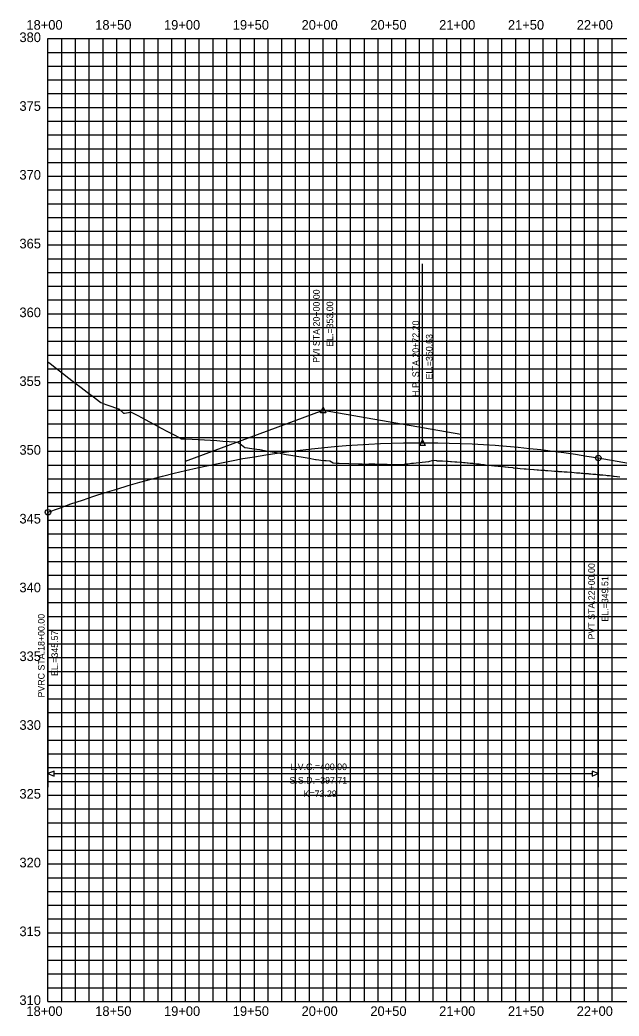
# Model space of a CAD drawing. Extents: x -797 to 1040, y -6256 to -5532.
# Drawn here: x 202 to 637, y -6256 to -5532 of the extents above; entities that cross this region are included whole.
import ezdxf

# ---------------------------------------------------------------- set-up
doc = ezdxf.new("R2010")
doc.units = 0
for name, color, linetype in [('CT_Pro_Grid_Frame', 7, 'Continuous'), ('CT_Pro_screen_Major', 7, 'Continuous'), ('CT_Pro_screen_Minor', 7, 'Continuous'), ('HM-SMOD-USR DEF1', 7, 'Continuous'), ('HR-GMSC-HOR_VER ALN', 7, 'Continuous'), ('HR-GMSC-PVCPVT SYMB', 7, 'Continuous'), ('HR-GPRO-PVCPVIPVT LDR', 7, 'Continuous'), ('HR-GPRO-PVCPVT TXT', 7, 'Continuous'), ('HR-GPRO-PVI SYMB', 7, 'Continuous'), ('HR-GPRO-PVI TXT', 7, 'Continuous'), ('HR-GPRO-STA_ELEV GRID TXT', 7, 'Continuous')]:
    doc.layers.add(name, color=color, linetype=linetype)

msp = doc.modelspace()

# ---------------------------------------------------------------- linework, layer by layer
at = {"layer": 'CT_Pro_Grid_Frame'}
for p, q in [((222.2, -5545.62), (1022.2, -5545.62)), ((222.2, -6245.62), (222.2, -5545.62)), ((222.2, -6245.62), (1022.2, -6245.62))]:
    msp.add_line(p, q, dxfattribs=at)
at = {"layer": 'CT_Pro_screen_Major'}
for p, q in [((272.2, -6245.62), (272.2, -5545.62)), ((322.2, -6245.62), (322.2, -5545.62)), ((372.2, -6245.62), (372.2, -5545.62)), ((422.2, -6245.62), (422.2, -5545.62)), ((472.2, -6245.62), (472.2, -5545.62)), ((522.2, -6245.62), (522.2, -5545.62)), ((572.2, -6245.62), (572.2, -5545.62)), ((622.2, -6245.62), (622.2, -5545.62)), ((222.2, -5595.62), (1022.2, -5595.62)), ((222.2, -5645.62), (1022.2, -5645.62)), ((222.2, -5695.62), (1022.2, -5695.62)), ((222.2, -5745.62), (1022.2, -5745.62)), ((222.2, -5795.62), (1022.2, -5795.62)), ((222.2, -5845.62), (1022.2, -5845.62)), ((222.2, -5895.62), (1022.2, -5895.62)), ((222.2, -5945.62), (1022.2, -5945.62)), ((222.2, -5995.62), (1022.2, -5995.62)), ((222.2, -6045.62), (1022.2, -6045.62)), ((222.2, -6095.62), (1022.2, -6095.62)), ((222.2, -6145.62), (1022.2, -6145.62)), ((222.2, -6195.62), (1022.2, -6195.62))]:
    msp.add_line(p, q, dxfattribs=at)
at = {"layer": 'CT_Pro_screen_Minor'}
for p, q in [((232.2, -6245.62), (232.2, -5545.62)), ((242.2, -6245.62), (242.2, -5545.62)), ((252.2, -6245.62), (252.2, -5545.62)), ((262.2, -6245.62), (262.2, -5545.62)), ((282.2, -6245.62), (282.2, -5545.62)), ((292.2, -6245.62), (292.2, -5545.62)), ((302.2, -6245.62), (302.2, -5545.62)), ((312.2, -6245.62), (312.2, -5545.62)), ((332.2, -6245.62), (332.2, -5545.62)), ((342.2, -6245.62), (342.2, -5545.62)), ((352.2, -6245.62), (352.2, -5545.62)), ((362.2, -6245.62), (362.2, -5545.62)), ((382.2, -6245.62), (382.2, -5545.62)), ((392.2, -6245.62), (392.2, -5545.62)), ((402.2, -6245.62), (402.2, -5545.62)), ((412.2, -6245.62), (412.2, -5545.62)), ((432.2, -6245.62), (432.2, -5545.62)), ((442.2, -6245.62), (442.2, -5545.62)), ((452.2, -6245.62), (452.2, -5545.62)), ((462.2, -6245.62), (462.2, -5545.62)), ((482.2, -6245.62), (482.2, -5545.62)), ((492.2, -6245.62), (492.2, -5545.62)), ((502.2, -6245.62), (502.2, -5545.62)), ((512.2, -6245.62), (512.2, -5545.62)), ((532.2, -6245.62), (532.2, -5545.62)), ((542.2, -6245.62), (542.2, -5545.62)), ((552.2, -6245.62), (552.2, -5545.62)), ((562.2, -6245.62), (562.2, -5545.62)), ((582.2, -6245.62), (582.2, -5545.62)), ((592.2, -6245.62), (592.2, -5545.62)), ((602.2, -6245.62), (602.2, -5545.62)), ((612.2, -6245.62), (612.2, -5545.62)), ((632.2, -6245.62), (632.2, -5545.62)), ((222.2, -5555.62), (1022.2, -5555.62)), ((222.2, -5565.62), (1022.2, -5565.62)), ((222.2, -5575.62), (1022.2, -5575.62)), ((222.2, -5585.62), (1022.2, -5585.62)), ((222.2, -5605.62), (1022.2, -5605.62)), ((222.2, -5615.62), (1022.2, -5615.62)), ((222.2, -5625.62), (1022.2, -5625.62)), ((222.2, -5635.62), (1022.2, -5635.62)), ((222.2, -5655.62), (1022.2, -5655.62)), ((222.2, -5665.62), (1022.2, -5665.62)), ((222.2, -5675.62), (1022.2, -5675.62)), ((222.2, -5685.62), (1022.2, -5685.62)), ((222.2, -5705.62), (1022.2, -5705.62)), ((222.2, -5715.62), (1022.2, -5715.62)), ((222.2, -5725.62), (1022.2, -5725.62)), ((222.2, -5735.62), (1022.2, -5735.62)), ((222.2, -5755.62), (1022.2, -5755.62)), ((222.2, -5765.62), (1022.2, -5765.62)), ((222.2, -5775.62), (1022.2, -5775.62)), ((222.2, -5785.62), (1022.2, -5785.62)), ((222.2, -5805.62), (1022.2, -5805.62)), ((222.2, -5815.62), (1022.2, -5815.62)), ((222.2, -5825.62), (1022.2, -5825.62)), ((222.2, -5835.62), (1022.2, -5835.62)), ((222.2, -5855.62), (1022.2, -5855.62)), ((222.2, -5865.62), (1022.2, -5865.62)), ((222.2, -5875.62), (1022.2, -5875.62)), ((222.2, -5885.62), (1022.2, -5885.62)), ((222.2, -5905.62), (1022.2, -5905.62)), ((222.2, -5915.62), (1022.2, -5915.62)), ((222.2, -5925.62), (1022.2, -5925.62)), ((222.2, -5935.62), (1022.2, -5935.62)), ((222.2, -5955.62), (1022.2, -5955.62)), ((222.2, -5965.62), (1022.2, -5965.62)), ((222.2, -5975.62), (1022.2, -5975.62)), ((222.2, -5985.62), (1022.2, -5985.62)), ((222.2, -6005.62), (1022.2, -6005.62)), ((222.2, -6015.62), (1022.2, -6015.62)), ((222.2, -6025.62), (1022.2, -6025.62)), ((222.2, -6035.62), (1022.2, -6035.62)), ((222.2, -6055.62), (1022.2, -6055.62)), ((222.2, -6065.62), (1022.2, -6065.62)), ((222.2, -6075.62), (1022.2, -6075.62)), ((222.2, -6085.62), (1022.2, -6085.62)), ((222.2, -6105.62), (1022.2, -6105.62)), ((222.2, -6115.62), (1022.2, -6115.62)), ((222.2, -6125.62), (1022.2, -6125.62)), ((222.2, -6135.62), (1022.2, -6135.62)), ((222.2, -6155.62), (1022.2, -6155.62)), ((222.2, -6165.62), (1022.2, -6165.62)), ((222.2, -6175.62), (1022.2, -6175.62)), ((222.2, -6185.62), (1022.2, -6185.62)), ((222.2, -6205.62), (1022.2, -6205.62)), ((222.2, -6215.62), (1022.2, -6215.62)), ((222.2, -6225.62), (1022.2, -6225.62)), ((222.2, -6235.62), (1022.2, -6235.62))]:
    msp.add_line(p, q, dxfattribs=at)
at = {"layer": 'HM-SMOD-USR DEF1'}
msp.add_lwpolyline([(222.2, -5780.55), (223.8, -5781.82), (228.28, -5785.36), (232.77, -5788.87), (237.25, -5792.37), (241.73, -5795.84), (246.22, -5799.3), (250.7, -5802.73), (255.19, -5806.14), (259.67, -5809.54), (260.61, -5810.24), (264.15, -5811.49), (268.64, -5813.08), (273.12, -5814.68), (273.6, -5814.85), (276.97, -5817.82), (277.44, -5817.89), (277.61, -5817.91), (277.77, -5817.94), (282.09, -5817.25), (282.67, -5817.16), (286.57, -5819.19), (291.06, -5821.54), (295.54, -5823.9), (300.03, -5826.29), (304.51, -5828.7), (308.99, -5831.12), (309.16, -5831.21), (313.48, -5833.48), (317.96, -5835.86), (319.25, -5836.55), (320.48, -5836.57), (322.45, -5836.65), (326.93, -5836.85), (331.41, -5837.07), (335.9, -5837.32), (340.38, -5837.58), (344.87, -5837.86), (349.35, -5838.16), (353.83, -5838.48), (358.32, -5838.83), (360.2, -5838.98), (362.8, -5840.98), (365.3, -5842.93), (367.29, -5843.17), (371.77, -5843.77), (376.25, -5844.43), (380.74, -5845.17), (385.22, -5845.96), (389.71, -5846.83), (394.19, -5847.76), (395.37, -5848.03), (398.68, -5848.47), (403.16, -5849.13), (407.64, -5849.86), (412.13, -5850.65), (416.61, -5851.51), (417.13, -5851.62), (419.13, -5851.84), (420.46, -5851.99), (423.14, -5852.26), (424.48, -5852.38), (427.18, -5852.62), (429.38, -5854.02), (432.02, -5854.19), (433.79, -5854.29), (447.94, -5854.76), (448.68, -5854.8), (449.6, -5854.83), (450.26, -5854.85), (450.73, -5854.86), (451.73, -5854.87), (452.84, -5854.87), (453.65, -5854.87), (455.47, -5854.84), (457.91, -5854.78), (459.81, -5854.71), (477.75, -5855.24), (478.31, -5855.19), (479.24, -5855.11), (481.1, -5854.92), (482.59, -5854.77), (483.73, -5854.65), (486.41, -5854.36), (488, -5854.19), (491.87, -5853.78), (499.1, -5853.04), (502.29, -5852.18), (504.59, -5852.42), (504.94, -5852.46), (508.74, -5852.63), (508.94, -5852.64), (512.57, -5852.83), (513.16, -5852.88), (514.82, -5852.98), (515.59, -5853.04), (517.92, -5853.2), (518.4, -5853.24), (519.41, -5853.33), (522.13, -5853.54), (522.94, -5853.62), (524.15, -5853.72), (525.35, -5853.84), (527.02, -5853.99), (527.68, -5854.06), (529.16, -5854.2), (530.77, -5854.37), (531.45, -5854.44), (532.31, -5854.53), (533.58, -5854.66), (535.4, -5854.85), (535.98, -5854.91), (536.95, -5855.02), (537.75, -5855.11), (539.26, -5855.27), (540.23, -5855.38), (542.35, -5855.61), (542.79, -5855.66), (543.9, -5855.78), (544.5, -5855.85), (546.21, -5856.03), (546.76, -5856.1), (549.45, -5856.39), (549.69, -5856.41), (550.3, -5856.48), (552.78, -5856.75), (553.04, -5856.78), (554.32, -5856.91), (554.68, -5856.95), (556.64, -5857.15), (556.95, -5857.19), (559.98, -5857.5), (560.11, -5857.51), (560.37, -5857.53), (563.49, -5857.84), (563.59, -5857.85), (563.74, -5857.86), (565.33, -5858.01), (565.47, -5858.02), (568.27, -5858.28), (568.34, -5858.28), (569.77, -5858.41), (569.89, -5858.42), (572.05, -5858.6), (572.1, -5858.6), (572.19, -5858.61), (575.46, -5858.88), (575.52, -5858.88), (577.73, -5859.05), (577.75, -5859.06), (578.86, -5859.14), (578.87, -5859.14), (580.55, -5859.27), (580.56, -5859.27), (582.81, -5859.44), (583.06, -5859.46), (583.82, -5859.51), (583.93, -5859.52), (583.93, -5859.52), (585.62, -5859.64), (585.63, -5859.64), (588.16, -5859.83), (588.16, -5859.83), (588.32, -5859.84), (590.41, -5859.99), (590.42, -5859.99), (591.54, -5860.07), (592.81, -5860.16), (593.22, -5860.19), (593.24, -5860.19), (595.75, -5860.38), (595.76, -5860.38), (595.78, -5860.38), (597.31, -5860.49), (598.29, -5860.56), (598.3, -5860.56), (599.55, -5860.65), (599.57, -5860.66), (601.78, -5860.82), (601.81, -5860.82), (601.83, -5860.82), (602.93, -5860.91), (602.98, -5860.91), (604.63, -5861.04), (604.66, -5861.04), (606.3, -5861.17), (606.31, -5861.17), (606.37, -5861.17), (607.19, -5861.24), (608.83, -5861.37), (608.86, -5861.37), (609.68, -5861.44), (609.74, -5861.44), (610.8, -5861.53), (610.96, -5861.54), (611.03, -5861.55), (612.66, -5861.68), (613.47, -5861.75), (613.52, -5861.75), (614.73, -5861.86), (614.79, -5861.86), (615.3, -5861.91), (616.6, -5862.02), (616.71, -5862.03), (618.37, -5862.18), (618.49, -5862.19), (619.59, -5862.29), (619.79, -5862.31), (620.32, -5862.35), (620.39, -5862.36), (621.36, -5862.45), (621.85, -5862.5), (621.99, -5862.51), (623.08, -5862.61), (623.15, -5862.62), (624.29, -5862.73), (625.32, -5862.83), (625.44, -5862.84), (627.6, -5863.05), (627.71, -5863.06), (627.77, -5863.06), (628.79, -5863.16), (629.2, -5863.21), (629.29, -5863.21), (630.24, -5863.31), (630.38, -5863.32), (632.27, -5863.51), (632.42, -5863.53), (633.29, -5863.62), (633.48, -5863.64), (633.56, -5863.64), (633.67, -5863.65), (635.78, -5863.87), (635.86, -5863.88), (636.02, -5863.89), (637.78, -5864.07)], dxfattribs=at)
at = {"layer": 'HR-GMSC-HOR_VER ALN'}
msp.add_line((622.2, -5850.49), (805.2, -5882.41), dxfattribs=at)
msp.add_lwpolyline([(222.2, -5889.9), (230.53, -5886.86), (238.86, -5883.9), (247.2, -5881.04), (255.53, -5878.28), (263.86, -5875.61), (272.2, -5873.04), (280.53, -5870.56), (288.86, -5868.17), (297.2, -5865.88), (305.53, -5863.69), (313.86, -5861.59), (322.2, -5859.58), (330.53, -5857.67), (338.86, -5855.86), (347.2, -5854.14), (355.53, -5852.51), (363.86, -5850.98), (372.2, -5849.54), (380.53, -5848.2), (388.86, -5846.95), (397.2, -5845.8), (405.53, -5844.74), (413.86, -5843.78), (430.53, -5842.14), (438.86, -5841.46), (447.2, -5840.87), (455.53, -5840.38), (463.86, -5839.99), (472.2, -5839.69), (480.53, -5839.48), (488.86, -5839.37), (497.2, -5839.36), (505.53, -5839.44), (513.86, -5839.61), (522.2, -5839.88), (530.53, -5840.24), (538.86, -5840.7), (547.2, -5841.25), (555.53, -5841.9), (563.86, -5842.64), (572.2, -5843.48), (580.53, -5844.41), (588.86, -5845.44), (597.2, -5846.56), (605.53, -5847.78), (613.86, -5849.09), (622.2, -5850.49)], dxfattribs=at)
at = {"layer": 'HR-GMSC-PVCPVT SYMB'}
for centre in [(622.2, -5850.49), (222.2, -5889.9)]:
    msp.add_circle(centre, 2, dxfattribs=at)
at = {"layer": 'HR-GPRO-PVCPVIPVT LDR'}
for p, q in [((422.2, -5815.62), (422.2, -5685.62)), ((494.4, -5839.35), (494.4, -5709.35)), ((322.2, -5852.76), (422.2, -5815.62)), ((422.2, -5815.62), (522.2, -5833.06)), ((622.2, -5850.49), (622.2, -6050.49)), ((622.2, -5850.49), (622.2, -6089.9)), ((222.2, -5889.9), (222.2, -6089.9)), ((222.2, -5889.9), (222.2, -6089.9))]:
    msp.add_line(p, q, dxfattribs=at)
for points in [[(222.2, -6079.9), (226.63, -6081.74), (226.63, -6078.07)], [(622.2, -6079.9), (617.76, -6078.07), (617.76, -6081.74)]]:
    msp.add_lwpolyline(points, close=True, dxfattribs=at)
msp.add_lwpolyline([(226.63, -6079.9), (617.76, -6079.9)], dxfattribs=at)
at = {"layer": 'HR-GPRO-PVI SYMB'}
for points in [[(422.2, -5813.62), (424.2, -5817.62), (420.2, -5817.62)], [(494.4, -5837.35), (496.4, -5841.35), (492.4, -5841.35)]]:
    msp.add_lwpolyline(points, close=True, dxfattribs=at)

# ---------------------------------------------------------------- texts
at = {"layer": 'HM-SMOD-USR DEF1'}
msp.add_text('-', height=0.0001, dxfattribs=at).set_placement((222.2, -6245.62))
at = {"layer": 'HR-GPRO-PVCPVT TXT'}
for s, p in [('PVT STA.22+00.00', (619.7, -5982.43)), ('EL.=349.51', (629.5, -5969.47)), ('PVRC STA.18+00.00', (219.7, -6024.64)), ('EL.=345.57', (229.5, -6008.96))]:
    msp.add_text(s, height=4.8, rotation=90, dxfattribs=at).set_placement(p)
for s, p in [('L.V.C.=400.00', (398.32, -6077.4)), ('S.S.D.=397.71', (397.76, -6087.2)), ('K=73.29', (408.01, -6097))]:
    msp.add_text(s, height=4.8, dxfattribs=at).set_placement(p)
at = {"layer": 'HR-GPRO-PVI TXT'}
for s, p in [('PVI STA.20+00.00', (419.7, -5781.28)), ('EL.=353.00', (429.5, -5769.68)), ('H.P. STA.20+72.20', (491.9, -5806.05)), ('EL.=350.63', (501.7, -5793.41))]:
    msp.add_text(s, height=4.8, rotation=90, dxfattribs=at).set_placement(p)
at = {"layer": 'HR-GPRO-STA_ELEV GRID TXT'}
for s, p in [('18+00', (206.53, -5539.12)), ('18+50', (256.53, -5539.12)), ('19+00', (306.53, -5539.12)), ('19+50', (356.53, -5539.12)), ('20+00', (406.53, -5539.12)), ('20+50', (456.53, -5539.12)), ('21+00', (506.53, -5539.12)), ('21+50', (556.53, -5539.12)), ('22+00', (606.53, -5539.12)), ('380', (201.44, -5548.12)), ('380', (201.44, -5548.12)), ('375', (201.44, -5598.12)), ('370', (201.44, -5648.12)), ('365', (201.44, -5698.12)), ('360', (201.44, -5748.12)), ('355', (201.44, -5798.12)), ('350', (201.44, -5848.12)), ('345', (201.44, -5898.12)), ('340', (201.44, -5948.12)), ('335', (201.44, -5998.12)), ('330', (201.44, -6048.12)), ('325', (201.44, -6098.12)), ('320', (201.44, -6148.12)), ('315', (201.44, -6198.12)), ('310', (201.44, -6248.12)), ('18+00', (206.53, -6256.12)), ('18+50', (256.53, -6256.12)), ('19+00', (306.53, -6256.12)), ('19+50', (356.53, -6256.12)), ('20+00', (406.53, -6256.12)), ('20+50', (456.53, -6256.12)), ('21+00', (506.53, -6256.12)), ('21+50', (556.53, -6256.12)), ('22+00', (606.53, -6256.12))]:
    msp.add_text(s, height=7, dxfattribs=at).set_placement(p)

doc.saveas('drawing.dxf')
